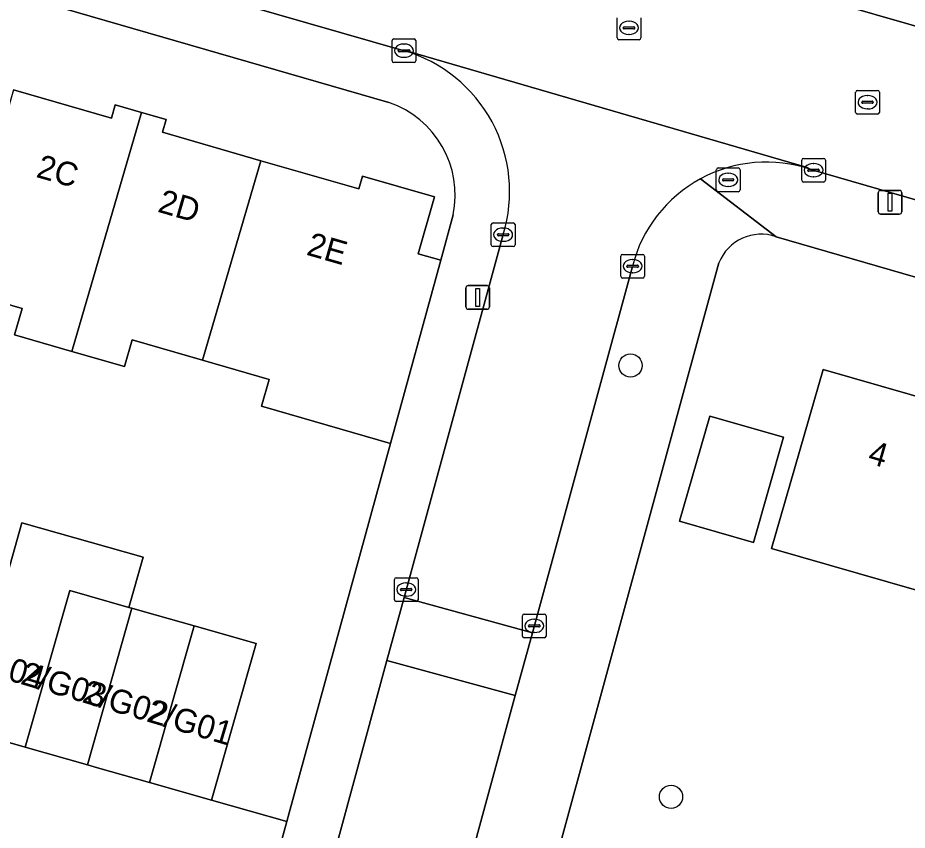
# Model space of a CAD drawing. Extents: x 159817 to 160765, y 380688 to 381638.
# Drawn here: x 160313.5 to 160351.02, y 381147.93 to 381182.22 of the extents above; entities that cross this region are included whole.
import ezdxf

# ---------------------------------------------------------------- set-up
doc = ezdxf.new("R2010")
doc.units = 0
for name, color, linetype in [('IMGEO_Boom', 7, 'Continuous'), ('IMGEO_Brandkraan', 7, 'Continuous'), ('IMGEO_Erf', 7, 'Continuous'), ('IMGEO_Kolk', 7, 'Continuous'), ('IMGEO_Lichtmast', 7, 'Continuous'), ('IMGEO_Muur', 7, 'Continuous'), ('IMGEO_Pand', 7, 'Continuous'), ('IMGEO_Pand_nummerreeks', 7, 'Continuous'), ('IMGEO_Rijbaan_lokaal_open', 7, 'Continuous'), ('IMGEO_Rioolput', 7, 'Continuous'), ('IMGEO_Voetpad_open', 7, 'Continuous')]:
    doc.layers.add(name, color=color, linetype=linetype)

msp = doc.modelspace()

# ---------------------------------------------------------------- linework, layer by layer
at = {"layer": 'IMGEO_Boom'}
for centre in [(160339.349, 381167.541), (160341.058, 381149.34)]:
    msp.add_circle(centre, 0.489, dxfattribs=at)
at = {"layer": 'IMGEO_Brandkraan'}
for p, q in [((160342.97, 381174.95), (160342.97, 381175.802)), ((160343.045, 381175.876), (160343.897, 381175.876)), ((160343.971, 381175.802), (160343.971, 381174.95)), ((160343.229, 381175.37), (160343.229, 381175.382)), ((160343.667, 381175.333), (160343.269, 381175.333)), ((160343.272, 381175.419), (160343.67, 381175.419)), ((160343.458, 381175.656), (160343.483, 381175.656)), ((160343.713, 381175.382), (160343.713, 381175.37)), ((160343.481, 381175.096), (160343.456, 381175.096)), ((160343.897, 381174.876), (160343.045, 381174.876))]:
    msp.add_line(p, q, dxfattribs=at)
for points in [[(160342.97, 381174.95), (160342.97, 381175.802)], [(160343.045, 381175.876), (160343.897, 381175.876)], [(160343.971, 381175.802), (160343.971, 381174.95)], [(160343.897, 381174.876), (160343.045, 381174.876)]]:
    msp.add_lwpolyline(points, dxfattribs=at)
for centre, radius, start, end in [((160343.047, 381175.8), 0.0765, 91.552, 178.448), ((160343.047, 381175.8), 0.0765, 91.552, 178.448), ((160343.895, 381175.8), 0.0765, 1.552, 88.448), ((160343.895, 381175.8), 0.0765, 1.552, 88.448), ((160343.269, 381175.379), 0.0403, 85.8775, 175.7526), ((160343.266, 381175.369), 0.0366, 178.938, 274.7102), ((160343.67, 381175.376), 0.043, 264.8664, 352.4533), ((160343.674, 381175.381), 0.0386, 1.7309, 96.639), ((160343.047, 381174.952), 0.0765, 181.552, 268.448), ((160343.047, 381174.952), 0.0765, 181.552, 268.448), ((160343.895, 381174.952), 0.0765, 271.552, 358.448), ((160343.895, 381174.952), 0.0765, 271.552, 358.448)]:
    msp.add_arc(centre, radius, start, end, dxfattribs=at)
for centre, major_axis, ratio, start_param, end_param in [((160343.457, 381175.376), (-0.387, 0.002), 0.722429, 4.712389, 7.853982), ((160343.482, 381175.376), (-0.39, 0.002), 0.717154, 1.570796, 4.712389)]:
    msp.add_ellipse(centre, major_axis=major_axis, ratio=ratio, start_param=start_param, end_param=end_param, dxfattribs=at)
at = {"layer": 'IMGEO_Erf'}
for points in [[(160329.156, 381178.647), (160278.3, 381193.36)], [(160313.324, 381179.174), (160317.448, 381177.983), (160317.609, 381178.543), (160318.713, 381178.224), (160319.759, 381177.922), (160319.603, 381177.382), (160323.754, 381176.183), (160327.884, 381174.99), (160328.041, 381175.534), (160331.087, 381174.655), (160330.393, 381172.254), (160331.343, 381171.98), (160331.87, 381173.902)], [(160407.146, 381155.127), (160345.496, 381172.978)], [(160343.078, 381171.876), (160335.866, 381145.432), (160340.821, 381144.08), (160341.675, 381147.212), (160344.775, 381146.366), (160343.92, 381143.235), (160347.143, 381142.348), (160347.152, 381142.38), (160347.93, 381145.236), (160351.365, 381144.299), (160350.575, 381141.403), (160351.308, 381141.202)], [(160313.075, 381158.789), (160313.677, 381160.905), (160318.794, 381159.448), (160318.191, 381157.332), (160318.315, 381157.297), (160318.747, 381157.174), (160320.935, 381156.551), (160323.555, 381155.805), (160321.675, 381149.201), (160324.851, 381148.297), (160324.95, 381148.659), (160329.224, 381164.249), (160324.421, 381165.636), (160323.782, 381165.821), (160324.108, 381166.949), (160321.293, 381167.762), (160318.323, 381168.619), (160317.999, 381167.496), (160315.781, 381168.136), (160313.367, 381168.833), (160313.69, 381169.952), (160310.912, 381170.754)]]:
    msp.add_lwpolyline(points, dxfattribs=at)
for points in [[(160387.463, 381147.685), (160381.456, 381149.414), (160375.447, 381151.142), (160369.441, 381152.87), (160363.433, 381154.598), (160357.426, 381156.326), (160351.418, 381158.055), (160345.296, 381159.816), (160347.471, 381167.376), (160353.593, 381165.615), (160359.601, 381163.887), (160365.608, 381162.159), (160371.616, 381160.43), (160377.622, 381158.703), (160383.631, 381156.974), (160389.638, 381155.246), (160395.644, 381153.518), (160401.771, 381151.756), (160400.922, 381148.803), (160406.891, 381147.056), (160404.695, 381139.55), (160398.613, 381141.351), (160399.462, 381144.234), (160393.469, 381145.958)], [(160341.418, 381160.966), (160342.696, 381165.408), (160345.81, 381164.512), (160344.532, 381160.07)], [(160321.675, 381149.201), (160319.054, 381149.947), (160316.867, 381150.57), (160316.435, 381150.693), (160313.815, 381151.439), (160311.195, 381152.185), (160308.575, 381152.931), (160305.955, 381153.678), (160303.335, 381154.424), (160300.715, 381155.17), (160298.095, 381155.916), (160295.475, 381156.662), (160292.855, 381157.408), (160290.236, 381158.154), (160289.094, 381158.456), (160287.711, 381153.232), (160287.458, 381152.277), (160323.338, 381142.779), (160324.851, 381148.297)]]:
    msp.add_lwpolyline(points, close=True, dxfattribs=at)
for centre, radius, start, end in [((160327.812, 381174.73), 4.141, 348.4708, 71.0658), ((160344.868, 381171.152), 1.931, 71.0189, 157.9832)]:
    msp.add_arc(centre, radius, start, end, dxfattribs=at)
at = {"layer": 'IMGEO_Kolk'}
for p, q in [((160329.292, 381180.4), (160329.292, 381181.252)), ((160329.367, 381181.326), (160330.219, 381181.326)), ((160329.78, 381181.106), (160329.805, 381181.106)), ((160330.293, 381181.252), (160330.293, 381180.4)), ((160329.551, 381180.82), (160329.551, 381180.832)), ((160329.989, 381180.783), (160329.591, 381180.783)), ((160329.594, 381180.869), (160329.992, 381180.869)), ((160330.035, 381180.832), (160330.035, 381180.82)), ((160330.219, 381180.326), (160329.367, 381180.326)), ((160329.803, 381180.546), (160329.778, 381180.546)), ((160346.571, 381175.357), (160346.571, 381176.209)), ((160346.646, 381176.283), (160347.498, 381176.283)), ((160347.572, 381176.209), (160347.572, 381175.357)), ((160346.83, 381175.777), (160346.83, 381175.789)), ((160347.268, 381175.74), (160346.87, 381175.74)), ((160346.873, 381175.826), (160347.271, 381175.826)), ((160347.059, 381176.063), (160347.084, 381176.063)), ((160347.314, 381175.789), (160347.314, 381175.777)), ((160347.082, 381175.503), (160347.057, 381175.503)), ((160347.498, 381175.283), (160346.646, 381175.283)), ((160333.476, 381172.635), (160333.476, 381173.487)), ((160333.551, 381173.561), (160334.403, 381173.561)), ((160334.477, 381173.487), (160334.477, 381172.635)), ((160333.778, 381173.104), (160334.176, 381173.104)), ((160333.964, 381173.341), (160333.989, 381173.341)), ((160333.735, 381173.055), (160333.735, 381173.067)), ((160334.173, 381173.018), (160333.775, 381173.018)), ((160333.987, 381172.781), (160333.962, 381172.781)), ((160334.219, 381173.067), (160334.219, 381173.055)), ((160334.403, 381172.561), (160333.551, 381172.561)), ((160338.939, 381171.305), (160338.939, 381172.157)), ((160339.014, 381172.231), (160339.866, 381172.231)), ((160339.427, 381172.011), (160339.452, 381172.011)), ((160339.94, 381172.157), (160339.94, 381171.305)), ((160339.198, 381171.725), (160339.198, 381171.737)), ((160339.636, 381171.688), (160339.238, 381171.688)), ((160339.241, 381171.774), (160339.639, 381171.774)), ((160339.682, 381171.737), (160339.682, 381171.725)), ((160339.866, 381171.231), (160339.014, 381171.231)), ((160339.45, 381171.451), (160339.425, 381171.451)), ((160329.388, 381157.659), (160329.388, 381158.511)), ((160329.463, 381158.585), (160330.315, 381158.585)), ((160330.389, 381158.511), (160330.389, 381157.659)), ((160329.647, 381158.079), (160329.647, 381158.091)), ((160329.69, 381158.128), (160330.088, 381158.128)), ((160329.876, 381158.365), (160329.901, 381158.365)), ((160330.131, 381158.091), (160330.131, 381158.079)), ((160330.085, 381158.042), (160329.687, 381158.042)), ((160329.899, 381157.805), (160329.874, 381157.805)), ((160330.315, 381157.585), (160329.463, 381157.585)), ((160334.789, 381156.126), (160334.789, 381156.978)), ((160334.864, 381157.052), (160335.716, 381157.052)), ((160335.79, 381156.978), (160335.79, 381156.126)), ((160335.091, 381156.595), (160335.489, 381156.595)), ((160335.277, 381156.832), (160335.302, 381156.832)), ((160335.048, 381156.546), (160335.048, 381156.558)), ((160335.486, 381156.509), (160335.088, 381156.509)), ((160335.3, 381156.272), (160335.275, 381156.272)), ((160335.532, 381156.558), (160335.532, 381156.546)), ((160335.716, 381156.052), (160334.864, 381156.052))]:
    msp.add_line(p, q, dxfattribs=at)
for points in [[(160329.292, 381180.4), (160329.292, 381181.252)], [(160329.367, 381181.326), (160330.219, 381181.326)], [(160330.293, 381181.252), (160330.293, 381180.4)], [(160330.219, 381180.326), (160329.367, 381180.326)], [(160346.571, 381175.357), (160346.571, 381176.209)], [(160346.646, 381176.283), (160347.498, 381176.283)], [(160347.572, 381176.209), (160347.572, 381175.357)], [(160347.498, 381175.283), (160346.646, 381175.283)], [(160333.476, 381172.635), (160333.476, 381173.487)], [(160333.551, 381173.561), (160334.403, 381173.561)], [(160334.477, 381173.487), (160334.477, 381172.635)], [(160334.403, 381172.561), (160333.551, 381172.561)], [(160338.939, 381171.305), (160338.939, 381172.157)], [(160339.014, 381172.231), (160339.866, 381172.231)], [(160339.94, 381172.157), (160339.94, 381171.305)], [(160339.866, 381171.231), (160339.014, 381171.231)], [(160329.388, 381157.659), (160329.388, 381158.511)], [(160329.463, 381158.585), (160330.315, 381158.585)], [(160330.389, 381158.511), (160330.389, 381157.659)], [(160330.315, 381157.585), (160329.463, 381157.585)], [(160334.789, 381156.126), (160334.789, 381156.978)], [(160334.864, 381157.052), (160335.716, 381157.052)], [(160335.79, 381156.978), (160335.79, 381156.126)], [(160335.716, 381156.052), (160334.864, 381156.052)]]:
    msp.add_lwpolyline(points, dxfattribs=at)
for centre, radius, start, end in [((160329.369, 381181.25), 0.0765, 91.552, 178.448), ((160329.369, 381181.25), 0.0765, 91.552, 178.448), ((160330.217, 381181.25), 0.0765, 1.552, 88.448), ((160330.217, 381181.25), 0.0765, 1.552, 88.448), ((160329.591, 381180.829), 0.0403, 85.8775, 175.7526), ((160329.588, 381180.819), 0.0366, 178.938, 274.7102), ((160329.992, 381180.826), 0.043, 264.8664, 352.4533), ((160329.996, 381180.831), 0.0386, 1.7309, 96.639), ((160329.369, 381180.402), 0.0765, 181.552, 268.448), ((160329.369, 381180.402), 0.0765, 181.552, 268.448), ((160330.217, 381180.402), 0.0765, 271.552, 358.448), ((160330.217, 381180.402), 0.0765, 271.552, 358.448), ((160346.648, 381176.207), 0.0765, 91.552, 178.448), ((160346.648, 381176.207), 0.0765, 91.552, 178.448), ((160347.496, 381176.207), 0.0765, 1.552, 88.448), ((160347.496, 381176.207), 0.0765, 1.552, 88.448), ((160346.87, 381175.786), 0.0403, 85.8775, 175.7526), ((160346.867, 381175.776), 0.0366, 178.938, 274.7102), ((160347.271, 381175.783), 0.043, 264.8664, 352.4533), ((160347.275, 381175.788), 0.0386, 1.7309, 96.639), ((160346.648, 381175.359), 0.0765, 181.552, 268.448), ((160346.648, 381175.359), 0.0765, 181.552, 268.448), ((160347.496, 381175.359), 0.0765, 271.552, 358.448), ((160347.496, 381175.359), 0.0765, 271.552, 358.448), ((160333.553, 381173.485), 0.0765, 91.552, 178.448), ((160333.553, 381173.485), 0.0765, 91.552, 178.448), ((160334.401, 381173.485), 0.0765, 1.552, 88.448), ((160334.401, 381173.485), 0.0765, 1.552, 88.448), ((160333.775, 381173.064), 0.0403, 85.8775, 175.7526), ((160334.18, 381173.066), 0.0386, 1.7309, 96.639), ((160333.772, 381173.054), 0.0366, 178.938, 274.7102), ((160334.176, 381173.061), 0.043, 264.8664, 352.4533), ((160333.553, 381172.637), 0.0765, 181.552, 268.448), ((160333.553, 381172.637), 0.0765, 181.552, 268.448), ((160334.401, 381172.637), 0.0765, 271.552, 358.448), ((160334.401, 381172.637), 0.0765, 271.552, 358.448), ((160339.016, 381172.155), 0.0765, 91.552, 178.448), ((160339.016, 381172.155), 0.0765, 91.552, 178.448), ((160339.864, 381172.155), 0.0765, 1.552, 88.448), ((160339.864, 381172.155), 0.0765, 1.552, 88.448), ((160339.238, 381171.734), 0.0403, 85.8775, 175.7526), ((160339.235, 381171.724), 0.0366, 178.938, 274.7102), ((160339.639, 381171.731), 0.043, 264.8664, 352.4533), ((160339.643, 381171.736), 0.0386, 1.7309, 96.639), ((160339.016, 381171.307), 0.0765, 181.552, 268.448), ((160339.016, 381171.307), 0.0765, 181.552, 268.448), ((160339.864, 381171.307), 0.0765, 271.552, 358.448), ((160339.864, 381171.307), 0.0765, 271.552, 358.448), ((160329.465, 381158.509), 0.0765, 91.552, 178.448), ((160329.465, 381158.509), 0.0765, 91.552, 178.448), ((160330.313, 381158.509), 0.0765, 1.552, 88.448), ((160330.313, 381158.509), 0.0765, 1.552, 88.448), ((160329.687, 381158.088), 0.0403, 85.8775, 175.7526), ((160329.684, 381158.078), 0.0366, 178.938, 274.7102), ((160330.088, 381158.085), 0.043, 264.8664, 352.4533), ((160330.092, 381158.09), 0.0386, 1.7309, 96.639), ((160329.465, 381157.661), 0.0765, 181.552, 268.448), ((160329.465, 381157.661), 0.0765, 181.552, 268.448), ((160330.313, 381157.661), 0.0765, 271.552, 358.448), ((160330.313, 381157.661), 0.0765, 271.552, 358.448), ((160334.866, 381156.976), 0.0765, 91.552, 178.448), ((160334.866, 381156.976), 0.0765, 91.552, 178.448), ((160335.714, 381156.976), 0.0765, 1.552, 88.448), ((160335.714, 381156.976), 0.0765, 1.552, 88.448), ((160335.088, 381156.555), 0.0403, 85.8775, 175.7526), ((160335.493, 381156.557), 0.0386, 1.7309, 96.639), ((160335.085, 381156.545), 0.0366, 178.938, 274.7102), ((160335.489, 381156.552), 0.043, 264.8664, 352.4533), ((160334.866, 381156.128), 0.0765, 181.552, 268.448), ((160334.866, 381156.128), 0.0765, 181.552, 268.448), ((160335.714, 381156.128), 0.0765, 271.552, 358.448), ((160335.714, 381156.128), 0.0765, 271.552, 358.448)]:
    msp.add_arc(centre, radius, start, end, dxfattribs=at)
for centre, major_axis, ratio, start_param, end_param in [((160329.779, 381180.826), (-0.387, 0.002), 0.722429, 4.712389, 7.853982), ((160329.804, 381180.826), (-0.39, 0.002), 0.717154, 1.570796, 4.712389), ((160347.058, 381175.783), (-0.387, 0.002), 0.722429, 4.712389, 7.853982), ((160347.083, 381175.783), (-0.39, 0.002), 0.717154, 1.570796, 4.712389), ((160333.963, 381173.061), (-0.387, 0.002), 0.722429, 4.712389, 7.853982), ((160333.988, 381173.061), (-0.39, 0.002), 0.717154, 1.570796, 4.712389), ((160339.426, 381171.731), (-0.387, 0.002), 0.722429, 4.712389, 7.853982), ((160339.451, 381171.731), (-0.39, 0.002), 0.717154, 1.570796, 4.712389), ((160329.875, 381158.085), (-0.387, 0.002), 0.722429, 4.712389, 7.853982), ((160329.9, 381158.085), (-0.39, 0.002), 0.717154, 1.570796, 4.712389), ((160335.276, 381156.552), (-0.387, 0.002), 0.722429, 4.712389, 7.853982), ((160335.301, 381156.552), (-0.39, 0.002), 0.717154, 1.570796, 4.712389)]:
    msp.add_ellipse(centre, major_axis=major_axis, ratio=ratio, start_param=start_param, end_param=end_param, dxfattribs=at)
at = {"layer": 'IMGEO_Lichtmast'}
for p, q in [((160349.8, 381174.033), (160349.8, 381174.833)), ((160349.8, 381174.833), (160349.8, 381174.033)), ((160349.9, 381174.933), (160350.69, 381174.933)), ((160350.69, 381174.933), (160349.9, 381174.933)), ((160350.79, 381174.833), (160350.79, 381174.033)), ((160350.79, 381174.033), (160350.79, 381174.833)), ((160350.69, 381173.933), (160349.9, 381173.933)), ((160349.9, 381173.933), (160350.69, 381173.933)), ((160332.506, 381170.913), (160333.296, 381170.913)), ((160333.296, 381170.913), (160332.506, 381170.913)), ((160332.406, 381170.013), (160332.406, 381170.813)), ((160332.406, 381170.813), (160332.406, 381170.013)), ((160333.396, 381170.813), (160333.396, 381170.013)), ((160333.396, 381170.013), (160333.396, 381170.813)), ((160333.296, 381169.913), (160332.506, 381169.913)), ((160332.506, 381169.913), (160333.296, 381169.913))]:
    msp.add_line(p, q, dxfattribs=at)
for points in [[(160350.22, 381174.808), (160350.37, 381174.808), (160350.37, 381174.058), (160350.22, 381174.058), (160350.22, 381174.808)], [(160332.826, 381170.788), (160332.976, 381170.788), (160332.976, 381170.038), (160332.826, 381170.038), (160332.826, 381170.788)]]:
    msp.add_lwpolyline(points, dxfattribs=at)
for centre, start, end in [((160349.9, 381174.833), 90, 180), ((160349.9, 381174.833), 90, 180), ((160350.69, 381174.833), 0, 90), ((160350.69, 381174.833), 360, 90), ((160349.9, 381174.033), 180, 270), ((160349.9, 381174.033), 180, 270), ((160350.69, 381174.033), 270, 0), ((160350.69, 381174.033), 270, 0), ((160332.506, 381170.813), 90, 180), ((160332.506, 381170.813), 90, 180), ((160333.296, 381170.813), 0, 90), ((160333.296, 381170.813), 360, 90), ((160332.506, 381170.013), 180, 270), ((160332.506, 381170.013), 180, 270), ((160333.296, 381170.013), 270, 0), ((160333.296, 381170.013), 270, 0)]:
    msp.add_arc(centre, 0.1, start, end, dxfattribs=at)
at = {"layer": 'IMGEO_Muur'}
for points in [[(160329.224, 381164.249), (160324.95, 381148.659)], [(160324.95, 381148.659), (160324.851, 381148.297)]]:
    msp.add_lwpolyline(points, dxfattribs=at)
at = {"layer": 'IMGEO_Pand'}
for points in [[(160315.781, 381168.136), (160318.713, 381178.224), (160317.609, 381178.543), (160317.448, 381177.983), (160313.324, 381179.174), (160310.912, 381170.754), (160313.69, 381169.952), (160313.367, 381168.833)], [(160315.781, 381168.136), (160317.999, 381167.496), (160318.323, 381168.619), (160321.293, 381167.762), (160323.754, 381176.183), (160319.603, 381177.382), (160319.759, 381177.922), (160318.713, 381178.224)], [(160323.754, 381176.183), (160321.293, 381167.762), (160324.108, 381166.949), (160323.782, 381165.821), (160324.421, 381165.636), (160329.224, 381164.249), (160331.343, 381171.98), (160330.393, 381172.254), (160331.087, 381174.655), (160328.041, 381175.534), (160327.884, 381174.99)], [(160353.593, 381165.615), (160347.471, 381167.376), (160345.296, 381159.816), (160351.418, 381158.055)], [(160341.418, 381160.966), (160344.532, 381160.07), (160345.81, 381164.512), (160342.696, 381165.408)], [(160315.695, 381158.043), (160318.191, 381157.332), (160318.794, 381159.448), (160313.677, 381160.905), (160313.075, 381158.789), (160311.195, 381152.185), (160313.815, 381151.439)], [(160318.315, 381157.297), (160318.191, 381157.332), (160315.695, 381158.043), (160313.815, 381151.439), (160316.435, 381150.693)], [(160316.435, 381150.693), (160316.867, 381150.57), (160319.054, 381149.947), (160320.935, 381156.551), (160318.747, 381157.174), (160318.315, 381157.297)], [(160320.935, 381156.551), (160319.054, 381149.947), (160321.675, 381149.201), (160323.555, 381155.805)]]:
    msp.add_lwpolyline(points, close=True, dxfattribs=at)
at = {"layer": 'IMGEO_Rijbaan_lokaal_open'}
for points in [[(160340.664, 381184.965), (160314.255, 381192.573), (160312.301, 381185.861), (160329.797, 381180.826), (160329.938, 381180.803), (160346.8, 381175.9), (160346.957, 381175.818), (160373.409, 381168.155), (160375.389, 381174.985), (160358.816, 381179.79), (160358.49, 381179.827), (160340.752, 381184.93)], [(160334.487, 381153.613), (160335.211, 381156.266), (160329.797, 381157.745), (160329.073, 381155.092)], [(160314.225, 381100.7), (160319.645, 381099.225), (160320.229, 381101.372), (160332.388, 381145.92), (160333.376, 381149.541), (160334.487, 381153.613), (160329.073, 381155.092), (160327.152, 381148.057), (160325.309, 381141.305), (160314.361, 381101.203)]]:
    msp.add_lwpolyline(points, close=True, dxfattribs=at)
for points in [[(160340.664, 381184.965), (160340.752, 381184.93), (160358.49, 381179.827), (160358.816, 381179.79)], [(160346.957, 381175.818), (160346.8, 381175.9), (160329.938, 381180.803), (160329.797, 381180.826)], [(160333.981, 381173.071), (160329.797, 381157.745), (160335.211, 381156.266), (160339.431, 381171.726)]]:
    msp.add_lwpolyline(points, dxfattribs=at)
for centre, radius, start, end in [((160328.055, 381174.88), 6.196, 343.0264, 73.6693), ((160345.085, 381170.293), 5.834, 71.2864, 118.5299), ((160345.085, 381170.294), 5.833, 118.5343, 165.7846)]:
    msp.add_arc(centre, radius, start, end, dxfattribs=at)
at = {"layer": 'IMGEO_Rioolput'}
for p, q in [((160338.785, 381181.363), (160338.785, 381182.215)), ((160339.786, 381182.215), (160339.786, 381181.363)), ((160339.044, 381181.783), (160339.044, 381181.795)), ((160339.482, 381181.746), (160339.084, 381181.746)), ((160339.087, 381181.832), (160339.485, 381181.832)), ((160339.273, 381182.069), (160339.298, 381182.069)), ((160339.528, 381181.795), (160339.528, 381181.783)), ((160339.296, 381181.509), (160339.271, 381181.509)), ((160339.712, 381181.289), (160338.86, 381181.289)), ((160348.923, 381179.15), (160349.775, 381179.15)), ((160348.848, 381178.224), (160348.848, 381179.076)), ((160349.336, 381178.93), (160349.361, 381178.93)), ((160349.849, 381179.076), (160349.849, 381178.224)), ((160349.107, 381178.644), (160349.107, 381178.656)), ((160349.545, 381178.607), (160349.147, 381178.607)), ((160349.15, 381178.693), (160349.548, 381178.693)), ((160349.359, 381178.37), (160349.334, 381178.37)), ((160349.591, 381178.656), (160349.591, 381178.644)), ((160349.775, 381178.15), (160348.923, 381178.15))]:
    msp.add_line(p, q, dxfattribs=at)
for points in [[(160338.785, 381181.363), (160338.785, 381182.215)], [(160339.786, 381182.215), (160339.786, 381181.363)], [(160339.712, 381181.289), (160338.86, 381181.289)], [(160348.923, 381179.15), (160349.775, 381179.15)], [(160348.848, 381178.224), (160348.848, 381179.076)], [(160349.849, 381179.076), (160349.849, 381178.224)], [(160349.775, 381178.15), (160348.923, 381178.15)]]:
    msp.add_lwpolyline(points, dxfattribs=at)
for centre, radius, start, end in [((160339.084, 381181.792), 0.0403, 85.8775, 175.7526), ((160339.081, 381181.782), 0.0366, 178.938, 274.7102), ((160339.485, 381181.789), 0.043, 264.8664, 352.4533), ((160339.489, 381181.794), 0.0386, 1.7309, 96.639), ((160338.862, 381181.365), 0.0765, 181.552, 268.448), ((160338.862, 381181.365), 0.0765, 181.552, 268.448), ((160339.71, 381181.365), 0.0765, 271.552, 358.448), ((160339.71, 381181.365), 0.0765, 271.552, 358.448), ((160348.925, 381179.074), 0.0765, 91.552, 178.448), ((160348.925, 381179.074), 0.0765, 91.552, 178.448), ((160349.773, 381179.074), 0.0765, 1.552, 88.448), ((160349.773, 381179.074), 0.0765, 1.552, 88.448), ((160349.147, 381178.653), 0.0403, 85.8775, 175.7526), ((160349.144, 381178.643), 0.0366, 178.938, 274.7102), ((160349.548, 381178.65), 0.043, 264.8664, 352.4533), ((160349.552, 381178.655), 0.0386, 1.7309, 96.639), ((160348.925, 381178.226), 0.0765, 181.552, 268.448), ((160348.925, 381178.226), 0.0765, 181.552, 268.448), ((160349.773, 381178.226), 0.0765, 271.552, 358.448), ((160349.773, 381178.226), 0.0765, 271.552, 358.448)]:
    msp.add_arc(centre, radius, start, end, dxfattribs=at)
for centre, major_axis, ratio, start_param, end_param in [((160339.272, 381181.789), (-0.387, 0.002), 0.722429, 4.712389, 7.853982), ((160339.297, 381181.789), (-0.39, 0.002), 0.717154, 1.570796, 4.712389), ((160349.335, 381178.65), (-0.387, 0.002), 0.722429, 4.712389, 7.853982), ((160349.36, 381178.65), (-0.39, 0.002), 0.717154, 1.570796, 4.712389)]:
    msp.add_ellipse(centre, major_axis=major_axis, ratio=ratio, start_param=start_param, end_param=end_param, dxfattribs=at)
at = {"layer": 'IMGEO_Voetpad_open'}
for points in [[(160329.797, 381180.826), (160312.301, 381185.861), (160309.697, 381186.611), (160281.102, 381194.84)], [(160278.3, 381193.36), (160329.156, 381178.647)], [(160376.002, 381167.404), (160373.409, 381168.155), (160346.957, 381175.818)], [(160342.299, 381175.418), (160345.496, 381172.978), (160407.146, 381155.127), (160412.248, 381153.013)], [(160345.496, 381172.978), (160342.299, 381175.418)], [(160331.87, 381173.902), (160331.343, 381171.98), (160329.224, 381164.249), (160324.95, 381148.659), (160324.851, 381148.297), (160323.338, 381142.779), (160323.099, 381141.909), (160323.01, 381141.585), (160322.79, 381141.612), (160322.546, 381140.716), (160311.809, 381101.359), (160314.225, 381100.7), (160314.361, 381101.203), (160325.309, 381141.305), (160327.152, 381148.057), (160329.073, 381155.092), (160329.797, 381157.745), (160333.981, 381173.071)], [(160339.431, 381171.726), (160335.211, 381156.266), (160334.487, 381153.613), (160333.376, 381149.541), (160332.388, 381145.92), (160320.229, 381101.372), (160319.645, 381099.225), (160323.013, 381098.308), (160323.218, 381099.059), (160324.03, 381102.036), (160335.349, 381143.537)], [(160335.349, 381143.537), (160335.866, 381145.432), (160343.078, 381171.876)]]:
    msp.add_lwpolyline(points, dxfattribs=at)
for centre, radius, start, end in [((160328.055, 381174.88), 6.196, 343.0264, 73.6693), ((160327.812, 381174.73), 4.141, 348.4708, 71.0658), ((160345.085, 381170.293), 5.834, 71.2864, 118.5299), ((160345.085, 381170.294), 5.833, 118.5343, 165.7846), ((160344.868, 381171.152), 1.931, 71.0189, 157.9832)]:
    msp.add_arc(centre, radius, start, end, dxfattribs=at)

# ---------------------------------------------------------------- texts
at = {"layer": 'IMGEO_Pand_nummerreeks'}
for s, rotation, p in [('2C', 344.1044, (160314.234, 381175.504)), ('2D', 343.8949, (160319.362, 381174.037)), ('2E', 343.8884, (160325.638, 381172.224)), ('4', 343.9515, (160349.316, 381163.431)), ('2/G04', 343.4759, (160310.969, 381154.885)), ('2/G03', 343.4759, (160313.574, 381154.113)), ('2/G02', 343.4761, (160316.171, 381153.342)), ('2/G01', 343.4761, (160318.887, 381152.536))]:
    msp.add_text(s, height=1, rotation=rotation, dxfattribs=at).set_placement(p)

doc.saveas('drawing.dxf')
